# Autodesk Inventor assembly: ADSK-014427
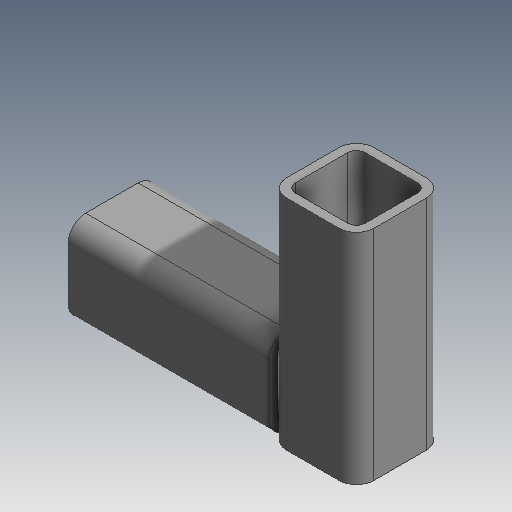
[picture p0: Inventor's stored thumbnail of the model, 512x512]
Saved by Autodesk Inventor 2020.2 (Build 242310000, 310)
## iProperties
_FrameDoc: Frame Assembly
_Version: 15.0.0
Part Number: ADSK-014427
Description: Phantom-Baugruppe
Document SubType Name: Baugruppe
Designer: lutzd
Mass: 262.506 g
Surface Area: 874.761 cm^2
Volume: 208.441 cm^3
Density: 1.25938 g/cm^3
DocNumber: ADSK-014427
Folder: .
Mass: 0,579 lb
Dimensions: 4,9x2x6,5 in
Title: Gestellbaugruppen
Author: lutzd
Revision Number: -
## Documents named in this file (5)
- D:\07 - DEMODATEN\OTX 2019 - Dataset - UPDATE - Dez2019\Designs\07-Packing machine\500665L\Frame\ADSK-014427.iam
- D:\07 - DEMODATEN\OTX 2019 - Dataset - UPDATE - Dez2019\Designs\07-Packing machine\500665L\Frame\ADSK-014430.ipt
- D:\07 - DEMODATEN\OTX 2019 - Dataset - UPDATE - Dez2019\Designs\07-Packing machine\500665L\Frame\ADSK-014429.ipt
- D:\07 - DEMODATEN\OTX 2019 - Dataset - UPDATE - Dez2019\Designs\07-Packing machine\500665L\Frame\ADSK-014428.ipt
- D:\07 - DEMODATEN\OTX 2019 - Dataset - UPDATE - Dez2019\Designs\07-Packing machine\Parts\ADSK-014431.ipt
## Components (4 placed, 3 different names)
1. Gestellreferenzmodell
2. DIN 50 x 50 x 5:1
3. DIN 50 x 50 x 5:2
4. Gerundete Ecken (mm) 5 x 40 x 40:1
